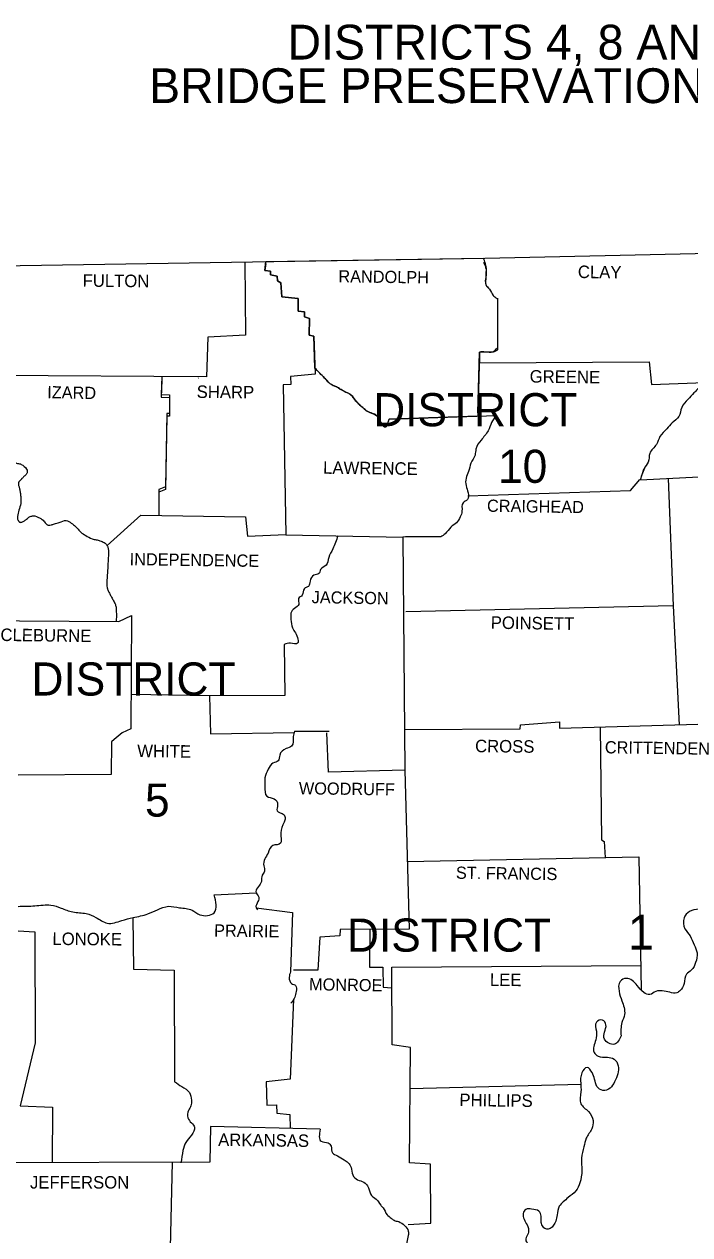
# Model space of a CAD drawing. Extents: x -13171 to 18763, y -8840 to 11152.
# Drawn here: x 13801 to 16044, y 7050 to 11129 of the extents above; entities that cross this region are included whole.
import ezdxf

# ---------------------------------------------------------------- set-up
doc = ezdxf.new("R2010")
doc.units = 0
for name, color, linetype in [('Level 1', 7, 'Continuous'), ('Level 2', 7, 'Continuous'), ('Level 3', 7, 'Continuous'), ('Level 42', 7, 'Continuous')]:
    doc.layers.add(name, color=color, linetype=linetype)

msp = doc.modelspace()

# ---------------------------------------------------------------- linework, layer by layer
at = {"layer": 'Level 1'}
for p, q in [((14615.8, 10328.9), (15347.9, 10340.3)), ((15396.7, 10202.4), (15396.7, 10032.6)), ((15878.1, 9593.9), (15889.9, 9630.1)), ((15881, 9605.6), (15892.8, 9634)), ((14711.9, 8746.6), (14828.3, 8746.6))]:
    msp.add_line(p, q, dxfattribs=at)
for points in [[(10745.4, 10313), (12327.5, 10312), (13715.8, 10314.9), (15353.7, 10340.4), (16112.9, 10358)], [(14544.5, 10327.8), (14546.5, 10081.1), (14419.3, 10074.3), (14415.4, 9941.2), (13702.7, 9945.1)], [(14780.7, 9970.4), (14777.4, 10078.2), (14761.8, 10081.1), (14762.7, 10137.9), (14745.1, 10142.7), (14745.1, 10159.4), (14724.6, 10162.3), (14724.6, 10204.4), (14668.8, 10210.3), (14665.9, 10257.2), (14655.1, 10264.1), (14653.1, 10279.7), (14630.6, 10284.6), (14631.6, 10296.4), (14612.1, 10299.3), (14615.8, 10328.9)], [(14615, 10322.8), (14612.1, 10299.3), (14631.6, 10296.4), (14630.6, 10284.6), (14653.1, 10279.7), (14655.1, 10264.1), (14665.9, 10257.2), (14668.8, 10210.3), (14724.6, 10204.4), (14724.6, 10162.3), (14745.1, 10159.4), (14745.1, 10142.7), (14762.7, 10137.9), (14761.8, 10081.1), (14777.4, 10078.2), (14781.3, 9950), (14698.2, 9942.2), (14699.1, 9914.8), (14673.7, 9913.8), (14682.5, 9408.9), (15076.8, 9400.1), (15083.6, 8615.5), (14826.3, 8608.6), (14821.4, 8740.7)], [(15396.7, 10205.4), (15396.7, 10040)], [(15335.1, 10024.4), (15329.9, 9808.8), (15030.8, 9798.3)], [(15330.2, 9819.9), (15335.1, 10024.4), (15335.1, 9988.2), (15907.5, 9991.1), (15915.3, 9914.8), (16094.8, 9921.3)], [(14264.8, 9942), (14262.8, 9881.5), (14290.2, 9879.6), (14291.1, 9816.9), (14281.4, 9816.9), (14277.4, 9570.4), (14254.9, 9560.6), (14254.9, 9478.4)], [(14264.7, 9929.5), (14262.8, 9872.7), (14290.2, 9870.7), (14291.1, 9808.1), (14281.4, 9808.1), (14277.4, 9561.6), (14254.9, 9551.8), (14254.9, 9473.7)], [(14387, 9936.3), (14388, 9937.3)], [(15030.8, 9798.3), (15391.5, 9811)], [(15878.1, 9593.9), (16620.7, 9632)], [(15296.1, 9539.9), (15843.9, 9557.7), (15876.2, 9594.8)], [(15971.8, 9598.7), (15988.7, 9169.2), (16008.6, 8768.4)], [(14080.7, 9371.9), (14194.3, 9474.5), (14546.5, 9469.6), (14553.3, 9404), (14682.5, 9409)], [(15205, 9402.1), (15085.6, 9402.1), (15076.8, 9400.1)], [(15988.7, 9169.2), (15087.6, 9148.7)], [(13617, 9119.3), (14119.9, 9116.4), (14163, 9136.9), (14160, 8754.4), (14130.7, 8741.7), (14104.3, 8719.2), (14095.5, 8710.4), (14094.5, 8600.8), (13780.4, 8598.8)], [(14677.6, 9039.1), (14679.6, 8866.9), (14425.2, 8865.9), (14160.9, 8870.9)], [(14425.2, 8865.9), (14429.1, 8737.8), (14710.8, 8742.8)], [(15082.5, 8752.4), (15473.1, 8754.4), (15474, 8768.1), (15605.1, 8777.9), (15605.1, 8757.3), (16188, 8773.3)], [(14711.9, 8746.6), (14707, 8728.9)], [(15742.1, 8761.1), (15747, 8380.6), (15755.8, 8374.8), (15758.9, 8320.6)], [(15083.6, 8615.5), (15098.3, 8079.3), (14865.5, 8078.3), (14864.5, 8056.8), (14797, 8052.9), (14791.1, 7941.3), (14708.9, 7941.3)], [(15092.1, 8307.2), (15872.2, 8322.9)], [(15872.2, 8322.9), (15880.4, 7874.7)], [(14440.8, 8195.7), (14582.7, 8202.6)], [(14166.9, 8119.4), (14168.8, 7944.3), (14306.8, 7941.3), (14307.8, 7565.6)], [(14582.7, 8151.7), (14705, 8136), (14698.2, 7936.4)], [(14965.3, 8078.7), (14964.3, 7952.1), (15009.3, 7952.1), (15011.2, 7884.6), (15040.1, 7881.6)], [(13780.4, 8074.4), (13837.2, 8070.5), (13838.1, 7696.7), (13787.3, 7484.4), (13895.9, 7479.5), (13894.8, 7292.5)], [(15095.4, 7084.2), (15171.7, 7089.1), (15170.7, 7287.8), (15099.3, 7292.6), (15103.2, 7681.1), (15041.6, 7689.9), (15039.6, 7951.1), (15878.9, 7957)], [(14708.9, 7842.5), (14697.2, 7574.4), (14616.9, 7565.6), (14618.9, 7486.4), (14651.2, 7487.3), (14652.2, 7460), (14696.2, 7455.1), (14697.6, 7407.8)], [(15101.8, 7543), (15676.7, 7557.3)], [(14798.9, 7405.2), (14429.1, 7414.9), (14427.1, 7294.6), (13678.7, 7291.7)], [(14299.1, 7294.1), (14291.1, 6910.1), (14427.1, 6899.3)]]:
    msp.add_lwpolyline(points, dxfattribs=at)
for points in [[(15347.9, 10340.3), (15349.9, 10335.8), (15351.7, 10331.2), (15354.8, 10322), (15356.8, 10312.6), (15357.2, 10310.3), (15357.4, 10307.9), (15357.6, 10303.2), (15357.5, 10296.6), (15357.2, 10290), (15356.9, 10283.4), (15356.6, 10276.8), (15356.5, 10273.7), (15356, 10264.6), (15355.9, 10258.4), (15356.2, 10255.4), (15356.4, 10253.9), (15356.5, 10253.1), (15356.6, 10252.3), (15357.4, 10249.9), (15357.9, 10248.7), (15358.6, 10247.6), (15360.3, 10245.5), (15362, 10243.6), (15365.9, 10239.7), (15367.8, 10237.8), (15369.3, 10235.7), (15372.5, 10230.6), (15375.5, 10225.4), (15378.6, 10220.2), (15380.3, 10217.6), (15382.1, 10215.1), (15384.2, 10212.7), (15386.6, 10210.4), (15389.1, 10208.4), (15396.7, 10202.4)], [(15348.8, 10327.7), (15357.6, 10303.2), (15356.6, 10276.8), (15356.6, 10252.3), (15369.3, 10235.7), (15382.1, 10215.1), (15391.8, 10206.3)], [(16112.9, 10358), (16117.8, 10314.9), (16131.5, 10292.4), (16133.5, 10251.3), (16150.1, 10233.7), (16178.5, 10216.1), (16203.9, 10187.8), (16209.8, 10154.5), (16202, 10120.2), (16200, 10082.1), (16196.1, 10048.8), (16190.2, 10018.5), (16166.7, 9994), (16144.2, 9976.4), (16123.7, 9955.9), (16109, 9934.3), (16083.6, 9910.9), (16058.1, 9886.4), (16037.6, 9864.9), (16017, 9837.5), (16007.3, 9807.2), (15984.8, 9785.6), (15967.1, 9766.1), (15943.7, 9739.6), (15931.9, 9713.2), (15909.4, 9682.9), (15904.5, 9653.5), (15889.9, 9630.1), (15888.9, 9626.1)], [(15392.8, 10037.1), (15380.1, 10024.4), (15355.6, 10024.4), (15335.1, 10024.4)], [(15396.7, 10032.6), (15394.9, 10030.9), (15393, 10029.3), (15389, 10026.7), (15384.6, 10025), (15382.4, 10024.5), (15381.3, 10024.4), (15380.1, 10024.4), (15355.6, 10024.4), (15335.1, 10024.4)], [(15030.8, 9798.3), (15029.3, 9794.1), (15027.6, 9789.2), (15023.8, 9779.4), (15019.6, 9772.4), (15017.4, 9771.1), (15016.3, 9771.2), (15015.2, 9771.9), (15014.7, 9772.4), (15014.3, 9772.8), (15013.3, 9773.8), (15011.5, 9776), (15007.8, 9781.2), (15004.1, 9786.9), (15002.3, 9789.8), (15000.5, 9792.5), (14997.8, 9796.7), (14995.2, 9800.9), (14992.6, 9805.1), (14989.7, 9809.1), (14986.6, 9812.2), (14982.8, 9814.5), (14974.3, 9817.8), (14965.4, 9820.6), (14957.4, 9824.8), (14952.2, 9828.7), (14947, 9832.8), (14941.8, 9837), (14936.9, 9841.4), (14926.4, 9851.5), (14916.3, 9861.9), (14914.4, 9864.2), (14912.7, 9866.6), (14909.4, 9871.7), (14906, 9876.5), (14901.7, 9880.5), (14900.3, 9881.4), (14899, 9882.2), (14890.5, 9886.6), (14884.8, 9889.3), (14879.2, 9892.3), (14866.4, 9899.6), (14853.7, 9906.9), (14848.3, 9909.6), (14842.7, 9911.9), (14837.2, 9914.4), (14832.2, 9917.7), (14830.9, 9918.8), (14829.7, 9919.9), (14827.3, 9922.1), (14822.7, 9926.8), (14813.6, 9936.3), (14797.1, 9953.2), (14780.7, 9970.4)], [(14792.1, 9958.8), (14813.6, 9936.3), (14832.2, 9917.7), (14853.7, 9906.9), (14879.2, 9892.3), (14901.7, 9880.5), (14916.3, 9861.9), (14936.9, 9841.4), (14957.4, 9824.8), (14989.7, 9809.1), (15000.5, 9792.5), (15015.2, 9771.9), (15030.8, 9798.3)], [(15391.5, 9811), (15376.2, 9786.6), (15364.4, 9759.2), (15341, 9727.9), (15323.4, 9697.6), (15320.4, 9677), (15306.7, 9649.6), (15298.9, 9622.2), (15290.1, 9598.8), (15290.1, 9574.3), (15296.9, 9549.8), (15295, 9527.3), (15280.3, 9516.6), (15276.4, 9488.2), (15270.5, 9468.6), (15257.8, 9449.1), (15239.2, 9434.4), (15219.6, 9411.9), (15205, 9402.1)], [(13665, 9725.9), (13674.5, 9722.3), (13684.4, 9720.3), (13694.3, 9719.5), (13704.1, 9719.1), (13710.2, 9721.1), (13716.3, 9725.5), (13722.1, 9728.9), (13724.9, 9729.2), (13727.6, 9727.9), (13733.1, 9722.3), (13737.4, 9716), (13741, 9709.3), (13744.2, 9702.5), (13753, 9682.9), (13759.8, 9668.5), (13763.5, 9661.4), (13765.5, 9657.9), (13767.7, 9654.5), (13772.3, 9650.8), (13778.5, 9649.2), (13785.1, 9648), (13788.3, 9647.1), (13791.2, 9645.7), (13808.8, 9630.1), (13811.3, 9621.6), (13810.7, 9617.2), (13808.8, 9613.4), (13805.1, 9609.4), (13801.1, 9605.6), (13797, 9601.8), (13793.1, 9597.8), (13791.4, 9595.9), (13785.8, 9590.4), (13782.8, 9586.5), (13781.8, 9584.4), (13781.4, 9582.1), (13781.7, 9577.5), (13782.8, 9572.9), (13784.2, 9568.2), (13785.3, 9563.5), (13787.4, 9550.8), (13789.2, 9538.1), (13789.2, 9513.6), (13783.3, 9491.1), (13778.5, 9470.6), (13778, 9466.1), (13778.6, 9461.7), (13780.4, 9457.3), (13781.7, 9455.1), (13783.3, 9453), (13785.4, 9451.3), (13787.6, 9450.5), (13792.5, 9451.2), (13801.9, 9455.9), (13806.8, 9459.4), (13811.5, 9463.6), (13816.2, 9467.7), (13821.5, 9470.6), (13826.5, 9471.8), (13831.8, 9472.3), (13842, 9470.6), (13852.1, 9465.7), (13861.6, 9459.8), (13866.8, 9454.9), (13871.5, 9449), (13876.3, 9443.8), (13879.1, 9442.1), (13880.6, 9441.5), (13882.2, 9441.2), (13892.4, 9442.2), (13902.7, 9445.1), (13919.3, 9450), (13942.8, 9456.9), (13959.5, 9448.1), (13974.1, 9436.3), (13978.6, 9431.8), (13982.9, 9427), (13987.1, 9422.2), (13991.7, 9417.7), (14008.4, 9406), (14029.9, 9395.2), (14036.3, 9393.1), (14043, 9391.7), (14049.7, 9390.3), (14056.3, 9388.4), (14070.2, 9382.4), (14076.1, 9377.9), (14078.6, 9375.1), (14079.8, 9373.5), (14080.8, 9371.8), (14082.4, 9368.2), (14084.7, 9357.6), (14084.9, 9350.5), (14084.7, 9343.4), (14083.7, 9318.9), (14081.8, 9288.6), (14079.8, 9255.3), (14079.4, 9247.2), (14079.4, 9239.1), (14080.4, 9231), (14081.4, 9227), (14082.7, 9223), (14087.9, 9212), (14093.5, 9201.5), (14100.4, 9189), (14107.2, 9176.1), (14110.3, 9164.5), (14110.8, 9158.6), (14111.1, 9152.6), (14111.6, 9134.5), (14110.3, 9116.5)], [(14858.1, 9405.1), (14841, 9361), (14827.3, 9331.6), (14818.5, 9306.2), (14799.9, 9291.5), (14794, 9277.8), (14777.4, 9272), (14764.7, 9252.4), (14758.8, 9234.8), (14745.1, 9227), (14738.3, 9205.4), (14725.5, 9193.7), (14726.5, 9174.1), (14711.9, 9160.4), (14700.1, 9144.8), (14700.1, 9123.2), (14705, 9094.9), (14714.8, 9078.2), (14723.6, 9056.7), (14722.6, 9043), (14698.2, 9043), (14677.6, 9039.1)], [(14707, 8728.9), (14702.1, 8696.7), (14683.5, 8687.9), (14662, 8666.3), (14657.1, 8646.8), (14639.4, 8638.9), (14622.8, 8618.4), (14612.1, 8590), (14612.1, 8560.7), (14618.9, 8527.4), (14643.4, 8518.6), (14655.1, 8499), (14653.1, 8478.5), (14676.6, 8464.8), (14680.5, 8453), (14676.6, 8440.3), (14665.9, 8404.1), (14666.8, 8379.7), (14664.9, 8368.9), (14638.5, 8362), (14622.8, 8335.6), (14612.1, 8317), (14608.1, 8292.6), (14611.1, 8275), (14603.2, 8261.3), (14600.3, 8240.7), (14590.5, 8223.1), (14581.7, 8206.5), (14591.5, 8186.9), (14588.6, 8173.2), (14582.7, 8151.7), (14587.6, 8144.8)], [(16237.2, 8689.8), (16241.1, 8661.4), (16224.5, 8631.1), (16218.6, 8600.8), (16221.5, 8570.4), (16190.2, 8553.8), (16162.8, 8534.2), (16178.5, 8510.8), (16207.8, 8489.2), (16237.2, 8472.6), (16255.8, 8456), (16260.7, 8415.9), (16265.6, 8390.4), (16275.3, 8355.2), (16279.3, 8330.7), (16261.6, 8301.4), (16241.1, 8295.5), (16219.6, 8302.4), (16194.1, 8304.3), (16173.6, 8284.8), (16158.9, 8257.4), (16144.2, 8230), (16133.5, 8206.5), (16122.7, 8181), (16101.2, 8151.7), (16074.8, 8146.8), (16043.5, 8139), (16024.9, 8117.4), (16027.8, 8081.2), (16045.4, 8056.8), (16059.1, 8026.5), (16068.9, 8000), (16064, 7966.8), (16050.3, 7942.3), (16032.7, 7927.6), (16024.9, 7896.3), (16012.2, 7872.8), (16000.4, 7865), (15976.9, 7867), (15951.5, 7871.9), (15930, 7869.9), (15909.4, 7859.1), (15888.9, 7866), (15867.4, 7889.5), (15849.7, 7907.1), (15830.2, 7913.9), (15809.6, 7903.2), (15805.7, 7870.9), (15815.5, 7837.6), (15824.3, 7792.6), (15815.5, 7765.2), (15812.6, 7720.2)], [(13780, 8156.5), (13837.2, 8158.5), (13891, 8160.5), (13925.2, 8150.7), (13964.3, 8138), (14010.3, 8132.1), (14042.6, 8119.4), (14080.8, 8099.8), (14129.7, 8108.6), (14167.9, 8118.4), (14217.8, 8131.1), (14250, 8144.8), (14287.2, 8156.6), (14324.4, 8151.7), (14366.5, 8143.9), (14392.9, 8128.2), (14440.8, 8135.1), (14440.8, 8195.7)], [(14698.2, 7936.4), (14694.2, 7916.9), (14702.1, 7896.3), (14715.8, 7889.5), (14717.7, 7869.9), (14712.8, 7850.3), (14708.9, 7842.5), (14700.1, 7830.8)], [(15812.6, 7720.2), (15790.1, 7691.8), (15756.8, 7709.4), (15756.8, 7732.9), (15761.7, 7757.4), (15749.9, 7773), (15729.4, 7766.2), (15729.4, 7735.9), (15727.4, 7706.5), (15721.6, 7664.4), (15735.3, 7651.7), (15766.6, 7647.8), (15789.1, 7641.9), (15802.8, 7619.4), (15801.8, 7592), (15791, 7565.6), (15775.4, 7544.1), (15750.9, 7536.3), (15731.4, 7549), (15723.5, 7574.4), (15714.7, 7596.9), (15698.1, 7613.6), (15680.5, 7595), (15676.6, 7560.7), (15677.5, 7531.4), (15677.5, 7491.3), (15703, 7464.8), (15718.6, 7434.5), (15713.7, 7407.1), (15695.2, 7374.8), (15687.3, 7346.5), (15679.5, 7308.3), (15680.5, 7266.2), (15673.6, 7225.1), (15659.9, 7197.7), (15634.5, 7175.2), (15617.9, 7160.6), (15604.2, 7145.9), (15597.3, 7116.5), (15592.4, 7096), (15573.8, 7071.5), (15559.2, 7069.6), (15547.4, 7079.4), (15543.5, 7096), (15543.5, 7112.6), (15535.7, 7129.3), (15511.2, 7136.1), (15491.6, 7135.1), (15482.8, 7121.4), (15495.6, 7083.3), (15500.4, 7058.8), (15493.6, 7025.5), (15497.5, 7021.6), (15462.3, 7003), (15433.9, 7000.1), (15410.4, 6993.3), (15387.9, 6978.6), (15377.2, 6957.1), (15361.5, 6939.4), (15347.8, 6922.8), (15329.2, 6915), (15308.7, 6918.9), (15281.3, 6921.8), (15265.6, 6902.3), (15270.5, 6873.9), (15289.1, 6857.3), (15316.5, 6849.4), (15344.9, 6851.4), (15372.3, 6854.3), (15397.7, 6840.6), (15392.8, 6814.2), (15368.4, 6801.5), (15332.2, 6797.6), (15302.8, 6800.5), (15267.6, 6792.7), (15250, 6770.2), (15259.8, 6735.9), (15297.9, 6722.2), (15315.5, 6689.9), (15316.5, 6659.6), (15303.8, 6619.5), (15286.2, 6600.9), (15251.9, 6593.1), (15225.5, 6588.2), (15221.6, 6543.2), (15209.9, 6520.7), (15189.3, 6513.8), (15160, 6528.5), (15142.4, 6535.4), (15120.8, 6545.1), (15093.4, 6561.8), (15072.9, 6558.8), (15078.8, 6515.8), (15080.7, 6513.8), (15104.2, 6481.5), (15127.7, 6456.1), (15138.4, 6425.8)], [(14307.8, 7565.6), (14332.2, 7549), (14357.7, 7529.4), (14364.5, 7503), (14362.6, 7484.4), (14354.7, 7468.8), (14352.8, 7444.3), (14364.5, 7426.7), (14375.3, 7412), (14364.5, 7385.6), (14345.9, 7361.1), (14336.1, 7333.7), (14329.3, 7292.6)], [(14798.9, 7405.2), (14801.9, 7365), (14825.3, 7359.2), (14835.1, 7348.4), (14840, 7325.9), (14856.7, 7316.1), (14879.2, 7302.4), (14892.9, 7292.6), (14902.6, 7277), (14908.5, 7251.6), (14924.2, 7234.9), (14945.7, 7227.1), (14961.3, 7208.5), (14971.1, 7182.1), (14986.8, 7170.3), (15002.4, 7149.8), (15010.3, 7141), (15024, 7117.5), (15037.7, 7105.8), (15047.4, 7098.9), (15063.1, 7094), (15082.7, 7081.3), (15095.4, 7061.7), (15095.4, 7047.1), (15090.5, 7024.6), (15086.6, 7001.1), (15084.6, 6974.7), (15082.7, 6951.2), (15091.5, 6931.6), (15086.6, 6902.3), (15076.8, 6886.6), (15075.8, 6865.1), (15072.9, 6832.8), (15069, 6814.2), (15060.2, 6783.9), (15047.4, 6768.2)]]:
    msp.add_spline(points, degree=3, dxfattribs=at)

# ---------------------------------------------------------------- texts
msp.add_text('1', height=117.4, dxfattribs=at).set_placement((15836, 8010.8))
at = {"layer": 'Level 2'}
for s, height, rotation, p in [('FULTON', 42.06, 359.4996, (13997.6, 10244.5)), ('RANDOLPH', 41.09, 359.2583, (14859.6, 10259.2)), ('CLAY', 42.06, 359.2258, (15666.8, 10273.9)), ('GREENE', 42.07, 359.2361, (15504.4, 9921.6)), ('IZARD', 41.08, 358.9258, (13878.2, 9868.8)), ('SHARP', 42.06, 359.3905, (14382.1, 9869.8)), ('LAWRENCE', 42.07, 359.2678, (14808.2, 9614.2)), ('CRAIGHEAD', 41.09, 359.1159, (15360.5, 9486.2)), ('INDEPENDENCE', 41.081, 359.2187, (14156.1, 9306.2)), ('JACKSON', 41.08, 359.1352, (14769.6, 9178)), ('POINSETT', 42.06, 359.1987, (15373.3, 9091.9)), ('CLEBURNE', 42.06, 359.2535, (13720.7, 9050.8)), ('WHITE', 42.07, 359.3139, (14181.6, 8659.5)), ('CROSS', 42.06, 359.3839, (15320.4, 8676.1)), ('CRITTENDEN', 41.09, 359.213, (15757.8, 8672.2)), ('WOODRUFF', 41.08, 359.2748, (14726.5, 8534.2)), ('ST. FRANCIS', 41.081, 359.2216, (15255.8, 8249.5)), ('PRAIRIE', 41.09, 359.2116, (14440.8, 8054.8)), ('LONOKE', 42.07, 359.4974, (13895.9, 8026.5)), ('MONROE', 41.08, 359.0331, (14760.8, 7873.8)), ('LEE', 42.07, 359.4327, (15370.3, 7888.5)), ('PHILLIPS', 42.06, 359.3179, (15267.6, 7483.4)), ('ARKANSAS', 42.06, 359.2678, (14454.5, 7349.4))]:
    msp.add_text(s, height=height, rotation=rotation, dxfattribs=at).set_placement(p)
msp.add_text('JEFFERSON', height=42.07, dxfattribs=at).set_placement((13820.5, 7205.6))
at = {"layer": 'Level 3'}
for s, height, p in [('DISTRICT', 111.54, (14977.3, 9774.3)), ('10', 111.54, (15398, 9583.5)), ('DISTRICT', 111.54, (13825.4, 8866.9)), ('5', 111.5, (14208, 8458.9)), ('DISTRICT', 111.54, (14888.9, 8003.9))]:
    msp.add_text(s, height=height, dxfattribs=at).set_placement(p)
at = {"layer": 'Level 42'}
for s, p in [('DISTRICTS 4, 8 AND 9 ', (14688.2, 11010)), ('BRIDGE PRESERVATION (2022) (S)', (14221.7, 10863.2))]:
    msp.add_text(s, height=117.24, dxfattribs=at).set_placement(p)

doc.saveas('drawing.dxf')
